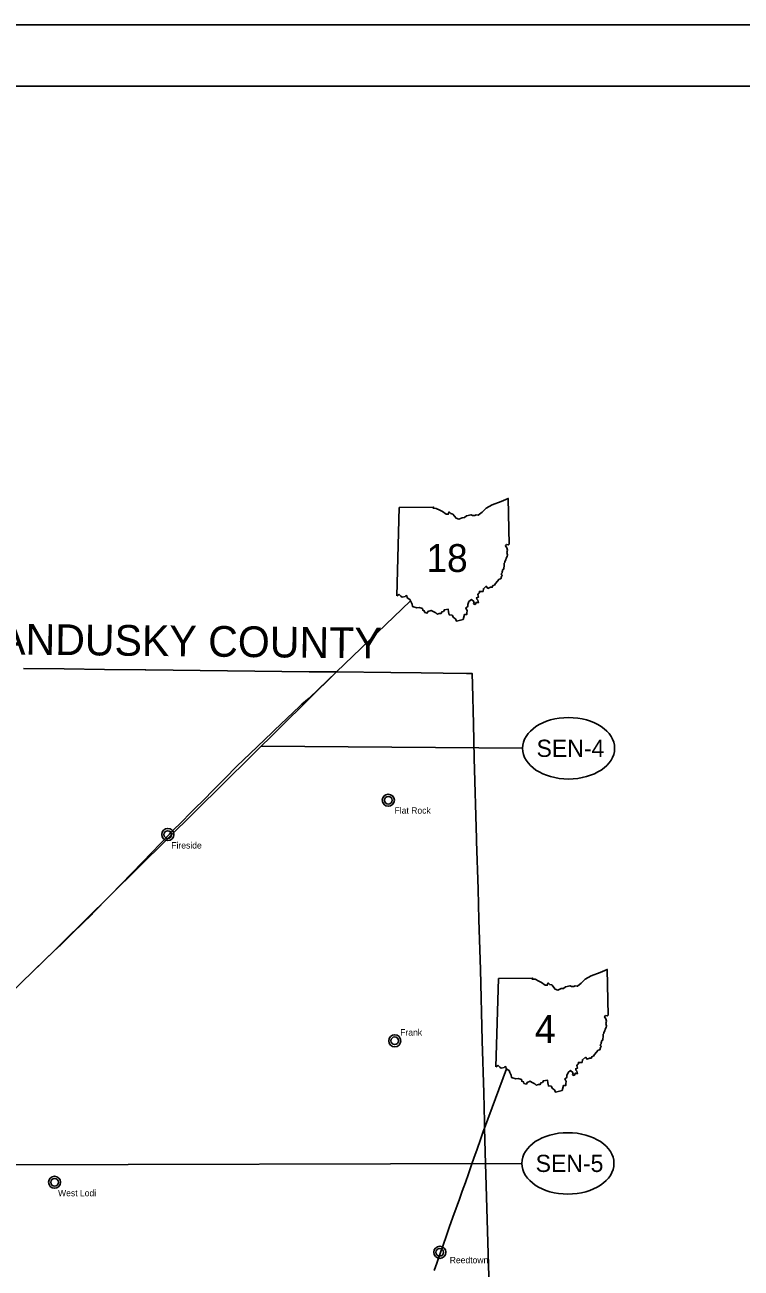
# Model space of a CAD drawing. Extents: x 0 to 882, y 0 to 440.
# Drawn here: x 468.1 to 584.7, y 237.6 to 440 of the extents above; entities that cross this region are included whole.
import ezdxf

# ---------------------------------------------------------------- set-up
doc = ezdxf.new("R2010")
doc.units = 0
for name, color, linetype in [('DV_X_Corp_Line', 7, 'Continuous'), ('GM_X_Adjacent_County_Text', 7, 'Continuous'), ('GM_X_County', 7, 'Continuous'), ('GM_X_State_Route', 7, 'Continuous'), ('PV_P_Text', 7, 'Continuous'), ('RD_P_Fence', 7, 'Continuous'), ('SH_Border', 7, 'Continuous'), ('SH_Cut_Line', 7, 'Continuous'), ('SH_Data', 7, 'Continuous')]:
    doc.layers.add(name, color=color, linetype=linetype)

msp = doc.modelspace()

# ---------------------------------------------------------------- linework, layer by layer
at = {"layer": 'DV_X_Corp_Line'}
for centre, radius in [((527.26, 313.76), 0.982), ((527.26, 313.76), 0.623), ((491.37, 308.18), 0.982), ((491.37, 308.18), 0.623), ((528.31, 274.6), 0.982), ((528.31, 274.6), 0.623), ((472.94, 251.56), 0.982), ((472.94, 251.56), 0.623), ((535.64, 240.16), 0.982), ((535.64, 240.16), 0.623)]:
    msp.add_circle(centre, radius, dxfattribs=at)
at = {"layer": 'GM_X_County'}
msp.add_lwpolyline([(467.9, 335.23), (474.53, 335.13), (481.09, 335.05), (487.66, 334.99), (487.78, 334.99), (501.08, 334.84), (514.39, 334.68), (518.84, 334.65), (527.68, 334.54), (532.59, 334.5), (536.19, 334.44), (539.99, 334.38), (540.92, 334.37), (540.95, 332.62), (541.12, 326.21), (541.26, 320.63), (541.59, 307.49), (541.6, 307.08), (541.86, 299.31), (542.02, 294.29), (542.28, 286.18), (542.54, 274.61), (542.82, 266.11), (542.91, 261.33), (542.93, 260.39), (543.09, 254.54), (543.13, 252.89), (543.68, 234.36)], dxfattribs=at)
at = {"layer": 'GM_X_State_Route'}
for p, q in [((518.84, 334.65), (530.8, 346.16)), ((542.93, 260.39), (546.5, 270.03))]:
    msp.add_line(p, q, dxfattribs=at)
for points in [[(500.66, 317.29), (502.63, 319.29), (504.76, 321.39), (508.35, 324.8), (508.72, 325.16), (512.78, 329.03), (513.16, 329.38), (514.36, 330.39), (518.84, 334.65)], [(479.07, 295.28), (482.05, 298.29), (487.24, 303.66), (491.64, 308.23), (491.88, 308.5), (493.92, 310.53), (494.74, 311.36), (495.19, 311.81), (497.77, 314.39), (498.23, 314.85), (500.66, 317.29)], [(473.83, 290.13), (475.98, 292.22), (478.98, 295.18), (479.07, 295.28)], [(471.41, 287.84), (473.74, 290.04), (473.83, 290.13)], [(423.36, 222.84), (427.54, 229.08), (432.09, 235.75), (433.12, 237.24), (441.18, 248.94), (446.03, 256.15), (446.36, 256.69), (446.66, 257.11), (447.13, 257.81), (449.99, 261.97), (452.05, 265.01), (454.26, 268.16), (454.83, 268.96), (457.29, 272.53), (459.34, 275.54), (460.09, 276.56), (460.6, 277.23), (461.17, 278), (463.6, 280.26), (465.54, 282.13), (471.41, 287.84)], [(534.73, 237.21), (535.14, 238.41), (535.77, 240.13), (536.19, 241.34), (536.72, 242.88), (537.19, 244.22), (537.78, 245.88), (538.31, 247.34), (538.48, 247.8), (538.83, 248.8), (539.3, 250.13), (539.8, 251.53), (540.29, 252.95), (540.75, 254.24), (540.86, 254.57), (541.18, 255.47), (541.7, 256.93), (542.27, 258.55), (542.72, 259.81), (542.93, 260.39)]]:
    msp.add_lwpolyline(points, dxfattribs=at)
at = {"layer": 'PV_P_Text'}
for p, q in [((528.65, 347.04), (529.05, 361.4)), ((528.65, 347.04), (529.05, 361.4)), ((544.77, 270.36), (545.17, 284.72)), ((544.77, 270.36), (545.17, 284.72))]:
    msp.add_line(p, q, dxfattribs=at)
for points in [[(529.05, 361.4), (534.62, 361.49), (534.54, 361.32), (535.06, 361.28), (535.62, 360.98), (536.09, 360.78), (536.67, 360.33), (537.02, 360.33), (537.16, 360.71), (537.43, 360.42), (537.74, 360.36), (538.28, 359.68), (538.73, 359.53), (539.27, 359.76), (539.67, 359.8), (539.96, 360.04), (540.73, 360.23), (540.94, 360.12), (541.35, 360.14), (541.55, 360.23), (541.9, 360.15), (542.53, 360.67), (543.17, 361.29), (544.15, 361.87), (545.62, 362.42), (546.78, 362.91), (546.95, 355.46)], [(529.05, 361.4), (534.62, 361.49), (534.54, 361.32), (535.06, 361.28), (535.62, 360.98), (536.09, 360.78), (536.67, 360.33), (537.02, 360.33), (537.16, 360.71), (537.43, 360.42), (537.74, 360.36), (538.28, 359.68), (538.73, 359.53), (539.27, 359.76), (539.67, 359.8), (539.96, 360.04), (540.73, 360.23), (540.94, 360.12), (541.35, 360.14), (541.55, 360.23), (541.9, 360.15), (542.53, 360.67), (543.17, 361.29), (544.15, 361.87), (545.62, 362.42), (546.78, 362.91), (546.95, 355.46)], [(546.95, 355.46), (546.78, 355.35), (546.51, 355.4), (546.33, 355.19), (546.55, 354.84), (546.66, 354.48), (546.57, 354.07), (546.66, 353.73), (546.6, 353.45), (546.43, 353.18), (546.37, 352.91), (546.23, 352.63), (546.24, 352.47), (546.1, 352.35), (546.13, 351.88), (546.06, 351.62), (546.08, 351.4), (545.86, 351.34), (545.91, 351.16), (545.77, 351.02), (545.8, 350.77), (545.64, 350.61), (545.8, 350.3), (545.67, 350.2), (545.57, 349.82), (545.29, 349.75), (544.72, 349.05), (544.52, 348.79), (544.3, 348.72), (544.17, 348.45), (543.9, 348.45), (543.48, 348.26), (543.21, 348.59), (542.73, 348.2), (542.68, 347.75), (542.08, 347.76), (542.1, 347.54), (541.97, 347.47), (541.85, 347.24), (541.92, 346.84), (541.64, 346.74), (541.67, 346.5), (541.85, 346.36), (541.93, 345.91), (541.63, 346.01), (541.39, 345.63), (541.14, 345.72), (541.22, 346.04), (540.79, 346.42), (540.39, 346.11), (540.18, 345.62), (540.18, 345.29), (539.88, 345.09), (540.07, 344.62), (540.04, 344.3), (540.04, 344), (539.67, 344.01), (539.44, 343.18)], [(546.95, 355.46), (546.78, 355.35), (546.51, 355.4), (546.33, 355.19), (546.55, 354.84), (546.66, 354.48), (546.57, 354.07), (546.66, 353.73), (546.6, 353.45), (546.43, 353.18), (546.37, 352.91), (546.23, 352.63), (546.24, 352.47), (546.1, 352.35), (546.13, 351.88), (546.06, 351.62), (546.08, 351.4), (545.86, 351.34), (545.91, 351.16), (545.77, 351.02), (545.8, 350.77), (545.64, 350.61), (545.8, 350.3), (545.67, 350.2), (545.57, 349.82), (545.29, 349.75), (544.72, 349.05), (544.52, 348.79), (544.3, 348.72), (544.17, 348.45), (543.9, 348.45), (543.48, 348.26), (543.21, 348.59), (542.73, 348.2), (542.68, 347.75), (542.08, 347.76), (542.1, 347.54), (541.97, 347.47), (541.85, 347.24), (541.92, 346.84), (541.64, 346.74), (541.67, 346.5), (541.85, 346.36), (541.93, 345.91), (541.63, 346.01), (541.39, 345.63), (541.14, 345.72), (541.22, 346.04), (540.79, 346.42), (540.39, 346.11), (540.18, 345.62), (540.18, 345.29), (539.88, 345.09), (540.07, 344.62), (540.04, 344.3), (540.04, 344), (539.67, 344.01), (539.44, 343.18)], [(539.44, 343.18), (538.79, 343.02), (538.34, 342.93), (538.18, 343.31), (537.86, 343.5), (537.65, 343.88), (537.19, 343.93), (537.08, 344.45), (537.02, 344.87), (536.39, 344.77), (536.22, 344.51), (535.99, 344.44), (535.86, 344.18), (535.55, 344.16), (535.23, 344.04), (535.01, 344.29), (534.47, 344.55), (534.23, 344.68), (533.72, 344.47), (533.61, 344.23), (533.21, 344.34), (533.12, 344.61), (532.87, 344.69), (532.82, 344.97), (532.3, 345.13), (531.9, 345.07), (531.2, 345.3), (531.15, 345.67), (530.91, 346.13), (530.79, 346.45), (530.34, 346.69), (530.25, 347.07), (530.11, 347.06), (529.98, 346.91), (529.49, 346.84), (529.29, 346.99), (529.01, 347.26), (528.65, 347.04)], [(539.44, 343.18), (538.79, 343.02), (538.34, 342.93), (538.18, 343.31), (537.86, 343.5), (537.65, 343.88), (537.19, 343.93), (537.08, 344.45), (537.02, 344.87), (536.39, 344.77), (536.22, 344.51), (535.99, 344.44), (535.86, 344.18), (535.55, 344.16), (535.23, 344.04), (535.01, 344.29), (534.47, 344.55), (534.23, 344.68), (533.72, 344.47), (533.61, 344.23), (533.21, 344.34), (533.12, 344.61), (532.87, 344.69), (532.82, 344.97), (532.3, 345.13), (531.9, 345.07), (531.2, 345.3), (531.15, 345.67), (530.91, 346.13), (530.79, 346.45), (530.34, 346.69), (530.25, 347.07), (530.11, 347.06), (529.98, 346.91), (529.49, 346.84), (529.29, 346.99), (529.01, 347.26), (528.65, 347.04)], [(545.17, 284.72), (550.74, 284.82), (550.66, 284.64), (551.18, 284.61), (551.74, 284.3), (552.21, 284.1), (552.79, 283.65), (553.14, 283.65), (553.28, 284.03), (553.55, 283.74), (553.86, 283.69), (554.41, 283), (554.85, 282.85), (555.39, 283.09), (555.79, 283.13), (556.09, 283.36), (556.85, 283.56), (557.06, 283.44), (557.47, 283.46), (557.67, 283.55), (558.03, 283.47), (558.65, 283.99), (559.29, 284.61), (560.27, 285.19), (561.74, 285.74), (562.9, 286.23), (563.07, 278.78)], [(545.17, 284.72), (550.74, 284.82), (550.66, 284.64), (551.18, 284.61), (551.74, 284.3), (552.21, 284.1), (552.79, 283.65), (553.14, 283.65), (553.28, 284.03), (553.55, 283.74), (553.86, 283.69), (554.41, 283), (554.85, 282.85), (555.39, 283.09), (555.79, 283.13), (556.09, 283.36), (556.85, 283.56), (557.06, 283.44), (557.47, 283.46), (557.67, 283.55), (558.03, 283.47), (558.65, 283.99), (559.29, 284.61), (560.27, 285.19), (561.74, 285.74), (562.9, 286.23), (563.07, 278.78)], [(563.07, 278.78), (562.9, 278.68), (562.63, 278.72), (562.45, 278.52), (562.68, 278.17), (562.78, 277.8), (562.69, 277.39), (562.78, 277.06), (562.72, 276.78), (562.55, 276.5), (562.49, 276.23), (562.35, 275.95), (562.36, 275.79), (562.22, 275.67), (562.25, 275.2), (562.18, 274.95), (562.2, 274.72), (561.98, 274.66), (562.03, 274.48), (561.89, 274.34), (561.92, 274.09), (561.76, 273.94), (561.92, 273.62), (561.8, 273.53), (561.69, 273.14), (561.41, 273.07), (560.84, 272.37), (560.64, 272.11), (560.42, 272.04), (560.29, 271.77), (560.02, 271.77), (559.6, 271.59), (559.33, 271.91), (558.85, 271.52), (558.8, 271.07), (558.2, 271.09), (558.22, 270.86), (558.09, 270.79), (557.97, 270.57), (558.04, 270.16), (557.76, 270.06), (557.79, 269.83), (557.97, 269.68), (558.05, 269.24), (557.75, 269.33), (557.51, 268.95), (557.26, 269.04), (557.34, 269.36), (556.92, 269.74), (556.51, 269.43), (556.3, 268.94), (556.3, 268.61), (556, 268.41), (556.19, 267.95), (556.16, 267.62), (556.17, 267.32), (555.79, 267.33), (555.56, 266.5)], [(563.07, 278.78), (562.9, 278.68), (562.63, 278.72), (562.45, 278.52), (562.68, 278.17), (562.78, 277.8), (562.69, 277.39), (562.78, 277.06), (562.72, 276.78), (562.55, 276.5), (562.49, 276.23), (562.35, 275.95), (562.36, 275.79), (562.22, 275.67), (562.25, 275.2), (562.18, 274.95), (562.2, 274.72), (561.98, 274.66), (562.03, 274.48), (561.89, 274.34), (561.92, 274.09), (561.76, 273.94), (561.92, 273.62), (561.8, 273.53), (561.69, 273.14), (561.41, 273.07), (560.84, 272.37), (560.64, 272.11), (560.42, 272.04), (560.29, 271.77), (560.02, 271.77), (559.6, 271.59), (559.33, 271.91), (558.85, 271.52), (558.8, 271.07), (558.2, 271.09), (558.22, 270.86), (558.09, 270.79), (557.97, 270.57), (558.04, 270.16), (557.76, 270.06), (557.79, 269.83), (557.97, 269.68), (558.05, 269.24), (557.75, 269.33), (557.51, 268.95), (557.26, 269.04), (557.34, 269.36), (556.92, 269.74), (556.51, 269.43), (556.3, 268.94), (556.3, 268.61), (556, 268.41), (556.19, 267.95), (556.16, 267.62), (556.17, 267.32), (555.79, 267.33), (555.56, 266.5)], [(555.56, 266.5), (554.91, 266.35), (554.46, 266.25), (554.3, 266.63), (553.98, 266.82), (553.77, 267.2), (553.31, 267.25), (553.2, 267.77), (553.15, 268.19), (552.51, 268.09), (552.34, 267.83), (552.11, 267.76), (551.98, 267.5), (551.68, 267.48), (551.35, 267.36), (551.13, 267.61), (550.59, 267.87), (550.35, 268), (549.84, 267.8), (549.74, 267.55), (549.33, 267.66), (549.24, 267.93), (548.99, 268.01), (548.94, 268.3), (548.42, 268.45), (548.02, 268.39), (547.32, 268.62), (547.27, 269), (547.04, 269.45), (546.91, 269.77), (546.47, 270.02), (546.38, 270.39), (546.23, 270.38), (546.1, 270.23), (545.61, 270.16), (545.41, 270.31), (545.13, 270.58), (544.77, 270.36)], [(555.56, 266.5), (554.91, 266.35), (554.46, 266.25), (554.3, 266.63), (553.98, 266.82), (553.77, 267.2), (553.31, 267.25), (553.2, 267.77), (553.15, 268.19), (552.51, 268.09), (552.34, 267.83), (552.11, 267.76), (551.98, 267.5), (551.68, 267.48), (551.35, 267.36), (551.13, 267.61), (550.59, 267.87), (550.35, 268), (549.84, 267.8), (549.74, 267.55), (549.33, 267.66), (549.24, 267.93), (548.99, 268.01), (548.94, 268.3), (548.42, 268.45), (548.02, 268.39), (547.32, 268.62), (547.27, 269), (547.04, 269.45), (546.91, 269.77), (546.47, 270.02), (546.38, 270.39), (546.23, 270.38), (546.1, 270.23), (545.61, 270.16), (545.41, 270.31), (545.13, 270.58), (544.77, 270.36)]]:
    msp.add_lwpolyline(points, dxfattribs=at)
at = {"layer": 'RD_P_Fence'}
msp.add_lwpolyline([(470.15, 286.61), (482.05, 298.29), (518.84, 334.65)], dxfattribs=at)
at = {"layer": 'SH_Border'}
msp.add_lwpolyline([(30, 430), (670, 430), (670, 10), (30, 10)], close=True, dxfattribs=at)
at = {"layer": 'SH_Cut_Line'}
msp.add_lwpolyline([(0, 0), (680, 0), (680, 440), (0, 440)], close=True, dxfattribs=at)
at = {"layer": 'SH_Data'}
for p, q in [((549.1, 322.24), (506.59, 322.54)), ((548.99, 254.63), (419.86, 254.3))]:
    msp.add_line(p, q, dxfattribs=at)
for centre in [(556.6, 322.22), (556.49, 254.64)]:
    msp.add_ellipse(centre, major_axis=(7.5, 0), ratio=0.666667, dxfattribs=at)

# ---------------------------------------------------------------- texts
at = {"layer": 'DV_X_Corp_Line'}
for s, p in [('Flat Rock', (528.28, 311.58)), ('Fireside', (491.94, 305.9)), ('Frank', (529.2, 275.45)), ('West Lodi', (473.51, 249.29)), ('Reedtown', (537.26, 238.38))]:
    msp.add_text(s, height=1.042, rotation=0, dxfattribs=at).set_placement(p)
at = {"layer": 'GM_X_Adjacent_County_Text'}
msp.add_text('SANDUSKY COUNTY', height=5, rotation=359.3732, dxfattribs=at).set_placement((459.28, 337.57))
at = {"layer": 'PV_P_Text'}
for s, height, p in [('18', 4.528, (533.45, 350.93)), ('4', 4.53, (551.12, 274.26))]:
    msp.add_text(s, height=height, dxfattribs=at).set_placement(p)
at = {"layer": 'SH_Data'}
for s, p in [('SEN-4', (551.39, 320.82)), ('SEN-5', (551.24, 253.24))]:
    msp.add_text(s, height=2.8, dxfattribs=at).set_placement(p)

doc.saveas('drawing.dxf')
